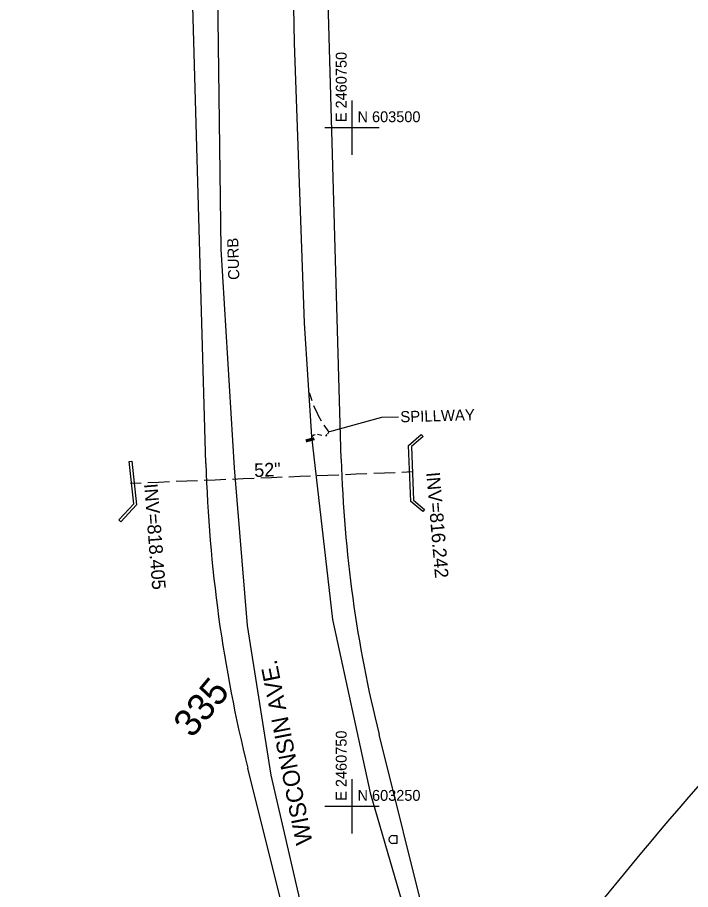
# Model space of a CAD drawing. Extents: x 2443269 to 2494951, y 591171 to 622130.
# Drawn here: x 2460626.7 to 2460874.7, y 603219.3 to 603540.6 of the extents above; entities that cross this region are included whole.
import ezdxf

# ---------------------------------------------------------------- set-up
doc = ezdxf.new("R2010")
doc.units = 0
for name, color, linetype in [('SURVEY - CENTERLINE - Preliminary', 7, 'Continuous'), ('SURVEY - CENTERLINE - Preliminary Text', 7, 'Continuous'), ('SURVEY - CONTROL - Grid', 7, 'Continuous'), ('SURVEY - CONTROL - Grid Text', 7, 'Continuous'), ('SURVEY - DRAINAGE - Bridges', 7, 'Continuous'), ('SURVEY - DRAINAGE - Pipes and Culverts', 7, 'Continuous'), ('SURVEY - DRAINAGE - Pipes and Culverts Text', 7, 'Continuous'), ('SURVEY - NON-TRANSPORTATION - Features', 7, 'Continuous'), ('SURVEY - PROPERTY - ROW Lines', 7, 'Continuous'), ('SURVEY - TRANSPORTATION - Features Text', 7, 'Continuous'), ('SURVEY - TRANSPORTATION - Roads', 7, 'Continuous'), ('SURVEY - TRANSPORTATION - Roads Text', 7, 'Continuous')]:
    doc.layers.add(name, color=color, linetype=linetype)

msp = doc.modelspace()

# ---------------------------------------------------------------- linework, layer by layer
at = {"layer": 'SURVEY - CENTERLINE - Preliminary'}
msp.add_arc((2461775.057, 602387.318), 1145.916, 130.716054, 156.410474, dxfattribs=at)
at = {"layer": 'SURVEY - CONTROL - Grid'}
for p, q in [((2460750, 603490), (2460750, 603510)), ((2460740, 603500), (2460760, 603500)), ((2460704.358, 603430.841), (2460704.358, 603430.841)), ((2460750, 603240), (2460750, 603260)), ((2460740, 603250), (2460760, 603250))]:
    msp.add_line(p, q, dxfattribs=at)
at = {"layer": 'SURVEY - DRAINAGE - Bridges'}
for p, q in [((2460775.491, 603386.916), (2460775.491, 603386.916)), ((2460735.058, 603386.176), (2460735.058, 603386.176)), ((2460770.839, 603382.914), (2460770.839, 603382.914)), ((2460668.881, 603377.133), (2460668.881, 603377.133)), ((2460670.626, 603361.005), (2460670.626, 603361.005)), ((2460771.626, 603362.307), (2460771.626, 603362.307)), ((2460776.083, 603358.566), (2460776.083, 603358.566)), ((2460664.756, 603354.797), (2460664.756, 603354.797))]:
    msp.add_line(p, q, dxfattribs=at)
at = {"layer": 'SURVEY - DRAINAGE - Pipes and Culverts'}
for p, q in [((2460734.186, 603402.429), (2460735.199, 603399.47)), ((2460735.839, 603397.624), (2460737.107, 603394.765)), ((2460737.107, 603394.765), (2460737.489, 603393.902)), ((2460737.489, 603393.902), (2460738.58, 603392.01)), ((2460739.579, 603390.331), (2460741.42, 603387.803)), ((2460735.931, 603386.674), (2460735.308, 603386.176)), ((2460736.388, 603386.767), (2460735.931, 603386.674)), ((2460738.802, 603386.615), (2460737.315, 603386.901)), ((2460740.687, 603386.892), (2460740.235, 603386.369)), ((2460740.235, 603386.369), (2460740.235, 603386.369)), ((2460741.42, 603387.741), (2460740.969, 603387.218)), ((2460741.42, 603387.803), (2460741.42, 603387.803)), ((2460735.308, 603386.176), (2460735.058, 603386.176)), ((2460703.488, 603370.324), (2460699.527, 603370.163)), ((2460703.488, 603370.324), (2460699.527, 603370.163)), ((2460709.926, 603370.587), (2460705.964, 603370.425)), ((2460709.926, 603370.587), (2460705.964, 603370.425)), ((2460713.887, 603370.748), (2460709.926, 603370.587)), ((2460713.887, 603370.748), (2460709.926, 603370.587)), ((2460720.325, 603371.011), (2460716.363, 603370.849)), ((2460720.325, 603371.011), (2460716.363, 603370.849)), ((2460724.286, 603371.173), (2460720.325, 603371.011)), ((2460724.286, 603371.173), (2460720.325, 603371.011)), ((2460730.723, 603371.435), (2460726.762, 603371.274)), ((2460730.723, 603371.435), (2460726.762, 603371.274)), ((2460734.685, 603371.597), (2460730.723, 603371.435)), ((2460734.685, 603371.597), (2460730.723, 603371.435)), ((2460741.122, 603371.859), (2460737.161, 603371.698)), ((2460741.122, 603371.859), (2460737.161, 603371.698)), ((2460745.084, 603372.021), (2460741.122, 603371.859)), ((2460745.084, 603372.021), (2460741.122, 603371.859)), ((2460751.521, 603372.283), (2460747.56, 603372.122)), ((2460751.521, 603372.283), (2460747.56, 603372.122)), ((2460755.483, 603372.445), (2460751.521, 603372.283)), ((2460755.483, 603372.445), (2460751.521, 603372.283)), ((2460761.92, 603372.708), (2460757.958, 603372.546)), ((2460761.92, 603372.708), (2460757.958, 603372.546)), ((2460765.881, 603372.869), (2460761.92, 603372.708)), ((2460765.881, 603372.869), (2460761.92, 603372.708)), ((2460772.319, 603373.132), (2460768.357, 603372.97)), ((2460772.319, 603373.132), (2460768.357, 603372.97)), ((2460672.292, 603369.052), (2460668.33, 603368.89)), ((2460672.292, 603369.052), (2460668.33, 603368.89)), ((2460678.729, 603369.315), (2460674.768, 603369.153)), ((2460678.729, 603369.315), (2460674.768, 603369.153)), ((2460682.691, 603369.476), (2460678.729, 603369.315)), ((2460682.691, 603369.476), (2460678.729, 603369.315)), ((2460689.128, 603369.739), (2460685.167, 603369.577)), ((2460689.128, 603369.739), (2460685.167, 603369.577)), ((2460693.09, 603369.9), (2460689.128, 603369.739)), ((2460693.09, 603369.9), (2460689.128, 603369.739)), ((2460699.527, 603370.163), (2460695.565, 603370.001)), ((2460699.527, 603370.163), (2460695.565, 603370.001))]:
    msp.add_line(p, q, dxfattribs=at)
for points in [[(2460776.143, 603386.158), (2460771.857, 603382.471), (2460772.609, 603362.788), (2460776.726, 603359.332), (2460776.083, 603358.566), (2460771.626, 603362.307), (2460770.839, 603382.914), (2460775.491, 603386.916)], [(2460664.029, 603355.484), (2460669.583, 603361.357), (2460667.886, 603377.025), (2460668.881, 603377.133), (2460670.626, 603361.005), (2460664.756, 603354.797)]]:
    msp.add_lwpolyline(points, close=True, dxfattribs=at)
at = {"layer": 'SURVEY - DRAINAGE - Pipes and Culverts Text'}
for p, q in [((2460741.746, 603388.111), (2460761.017, 603393.273)), ((2460761.017, 603393.273), (2460767.166, 603393.451))]:
    msp.add_line(p, q, dxfattribs=at)
at = {"layer": 'SURVEY - NON-TRANSPORTATION - Features'}
for p, q in [((2460765.013, 603239.217), (2460765.013, 603239.217)), ((2460763.555, 603237.759), (2460763.555, 603237.759))]:
    msp.add_line(p, q, dxfattribs=at)
msp.add_lwpolyline([(2460765.013, 603239.217), (2460766.472, 603239.217), (2460766.472, 603236.301), (2460765.013, 603236.301)], dxfattribs=at)
for start, end in [(90, 180), (180, 270)]:
    msp.add_arc((2460765.014, 603237.759), 1.458, start, end, dxfattribs=at)
at = {"layer": 'SURVEY - PROPERTY - ROW Lines'}
for points in [[(2460696.153, 603376.239), (2460696.153, 603376.243), (2460689.188, 603618.222)], [(2460746.014, 603377.853), (2460746.014, 603377.857), (2460739.05, 603619.836)], [(2460777.813, 603205.02), (2460759.985, 603276.377), (2460759.984, 603276.38)], [(2460729.417, 603192.745), (2460711.594, 603264.082), (2460711.593, 603264.085)]]:
    msp.add_lwpolyline(points, dxfattribs=at)
for centre, radius, start, end in [((2462042.468, 602244.972), 1543.443, 131.058594, 143.779356), ((2461220.818, 603391.519), 475, 181.64865, 194.02809), ((2461220.936, 603391.343), 525, 181.64865, 194.02809)]:
    msp.add_arc(centre, radius, start, end, dxfattribs=at)
at = {"layer": 'SURVEY - TRANSPORTATION - Roads'}
for points in [[(2460629.143, 603899.879), (2460657.74, 603851.631), (2460688.058, 603794.167), (2460702.354, 603757.664), (2460713.323, 603721.589), (2460723.264, 603669.833), (2460726.776, 603632.906), (2460727.628, 603583.281), (2460728.643, 603531.175), (2460732.342, 603427.91), (2460735.101, 603386.199)], [(2460706.64, 603374.718), (2460701.795, 603455.169), (2460700.481, 603549.233), (2460698.144, 603645.891), (2460688.969, 603703.416), (2460675.744, 603750.22), (2460654.901, 603799.387), (2460637.902, 603831.166), (2460607.664, 603881.624)], [(2460735.101, 603386.199), (2460742.843, 603318.819), (2460756.654, 603254.926), (2460772.883, 603199.314), (2460784.52, 603165.904), (2460807.167, 603123.358), (2460825.881, 603107.436), (2460845.411, 603100.923), (2460869.471, 603106.516), (2460890.031, 603124.157), (2460914.694, 603155.673), (2460951.477, 603198.17), (2460982.013, 603230.018), (2460992.114, 603234.479), (2461028.992, 603261.002), (2461182.495, 603394.479)], [(2460717.31, 602804.823), (2460755.087, 602883.507), (2460787.212, 602944.497), (2460815.088, 602993.112), (2460818.099, 603019.477), (2460812.224, 603050.474), (2460793.572, 603079.233), (2460766.789, 603118.503), (2460751, 603152.189), (2460733.361, 603204.587), (2460720.245, 603261.435), (2460711.505, 603316.576), (2460706.64, 603374.718)]]:
    msp.add_lwpolyline(points, dxfattribs=at)

# ---------------------------------------------------------------- texts
at = {"layer": 'SURVEY - CENTERLINE - Preliminary Text'}
msp.add_text('335', height=10, rotation=50.14259, dxfattribs=at).set_placement((2460691.029, 603274.803))
at = {"layer": 'SURVEY - CONTROL - Grid Text'}
for p in [(2460748, 603502), (2460748, 603252)]:
    msp.add_text('E 2460750', height=4, rotation=90, dxfattribs=at).set_placement(p)
for s, p in [('N 603500', (2460752, 603502)), ('N 603250', (2460752, 603252))]:
    msp.add_text(s, height=4, dxfattribs=at).set_placement(p)
at = {"layer": 'SURVEY - DRAINAGE - Pipes and Culverts Text'}
for s, height, rotation, p in [('SPILLWAY', 4.101, 1.65701, (2460767.84, 603391.419)), ('-', 10, 14.99623, (2460733.38, 603380.694)), ('52"', 5, 2.33554, (2460714.014, 603371.254)), ('INV=816.242', 5, 274.80402, (2460777.328, 603372.922)), ('INV=818.405', 5, 274.5036, (2460673.338, 603368.694))]:
    msp.add_text(s, height=height, rotation=rotation, dxfattribs=at).set_placement(p)
at = {"layer": 'SURVEY - TRANSPORTATION - Features Text'}
msp.add_text('CURB', height=4.101, rotation=91.65695, dxfattribs=at).set_placement((2460708.483, 603443.945))
at = {"layer": 'SURVEY - TRANSPORTATION - Roads Text'}
msp.add_text(' WISCONSIN AVE.', height=6.199, rotation=101.14999, dxfattribs=at).set_placement((2460735.951, 603234.244))

doc.saveas('drawing.dxf')
